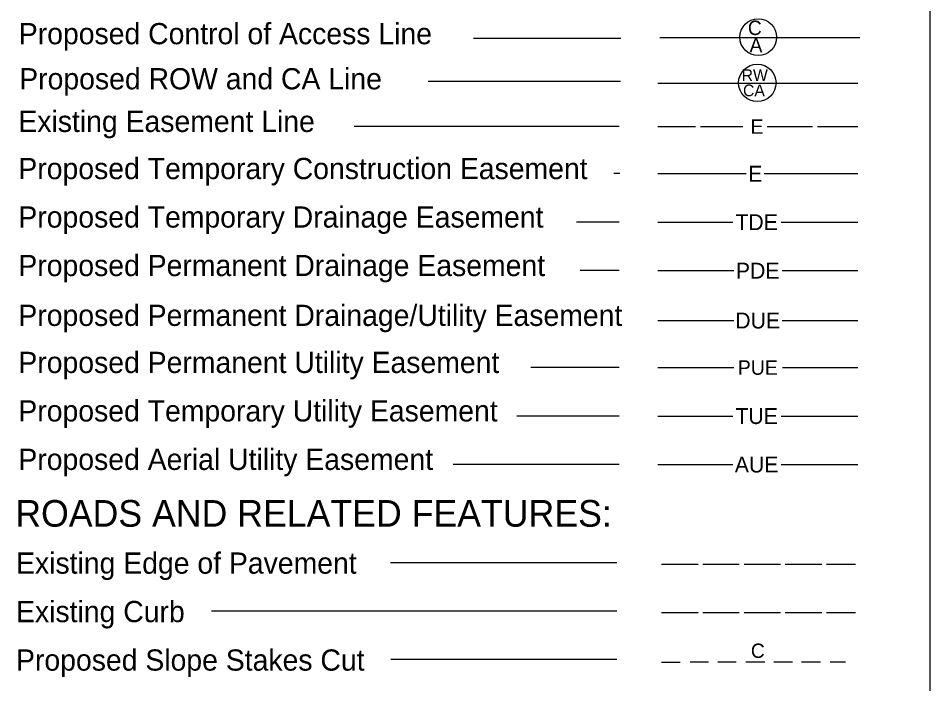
# Model space of a CAD drawing. Extents: x 1855058 to 1858918, y 1540202 to 1542502.
# Drawn here: x 1857589.3 to 1857968.6, y 1541681.9 to 1541959 of the extents above; entities that cross this region are included whole.
import ezdxf

# ---------------------------------------------------------------- set-up
doc = ezdxf.new("R2010")
doc.units = 0
for name, color, linetype in [('CTL Primary Horizontal CELL', 7, 'Continuous'), ('Exist Contamination Potential Cell', 7, 'Continuous'), ('Sheet Data Field CELL', 7, 'Continuous')]:
    doc.layers.add(name, color=color, linetype=linetype)

msp = doc.modelspace()

# ---------------------------------------------------------------- linework, layer by layer
at = {"layer": 'CTL Primary Horizontal CELL'}
for p, q in [((1857855.47, 1541833.13), (1857887.05, 1541833.13)), ((1857907.23, 1541833.13), (1857938.71, 1541833.13))]:
    msp.add_line(p, q, dxfattribs=at)
at = {"layer": 'Exist Contamination Potential Cell'}
msp.add_line((1857968.6, 1542464.27), (1857968.58, 1541439.27), dxfattribs=at)
at = {"layer": 'Sheet Data Field CELL'}
for p, q in [((1857840.04, 1541950.58), (1857778.79, 1541950.58)), ((1857856.22, 1541950.96), (1857939.45, 1541950.96)), ((1857839.94, 1541932.66), (1857759.87, 1541932.66)), ((1857855.48, 1541931.88), (1857938.72, 1541931.88)), ((1857839.3, 1541913.88), (1857729.07, 1541913.88)), ((1857855.47, 1541913.88), (1857871.12, 1541913.88)), ((1857873.14, 1541913.88), (1857890.8, 1541913.88)), ((1857900.89, 1541913.88), (1857919.81, 1541913.88)), ((1857921.82, 1541913.88), (1857938.71, 1541913.88)), ((1857839.69, 1541894.25), (1857837.15, 1541894.25)), ((1857855.47, 1541894.25), (1857858.11, 1541894.25)), ((1857858.11, 1541894.25), (1857892.16, 1541894.25)), ((1857899.73, 1541894.25), (1857933.78, 1541894.25)), ((1857933.78, 1541894.25), (1857938.71, 1541894.25)), ((1857839.3, 1541874.07), (1857821.65, 1541874.07)), ((1857855.47, 1541874.07), (1857858.85, 1541874.07)), ((1857858.85, 1541874.07), (1857886.6, 1541874.07)), ((1857906.78, 1541874.07), (1857934.52, 1541874.07)), ((1857934.52, 1541874.07), (1857938.71, 1541874.07)), ((1857839.3, 1541853.89), (1857823.15, 1541853.89)), ((1857855.47, 1541853.89), (1857859.31, 1541853.89)), ((1857859.31, 1541853.89), (1857887.05, 1541853.89)), ((1857907.23, 1541853.89), (1857934.98, 1541853.89)), ((1857934.98, 1541853.89), (1857938.71, 1541853.89)), ((1857839.3, 1541813.53), (1857802.56, 1541813.53)), ((1857855.47, 1541813.53), (1857859.35, 1541813.53)), ((1857859.35, 1541813.53), (1857887.09, 1541813.53)), ((1857907.27, 1541813.53), (1857935.02, 1541813.53)), ((1857935.02, 1541813.53), (1857938.71, 1541813.53)), ((1857839.3, 1541793.35), (1857796.79, 1541793.35)), ((1857855.47, 1541793.35), (1857858.85, 1541793.35)), ((1857858.85, 1541793.35), (1857886.6, 1541793.35)), ((1857906.78, 1541793.35), (1857934.52, 1541793.35)), ((1857934.52, 1541793.35), (1857938.71, 1541793.35)), ((1857839.3, 1541773.17), (1857770.23, 1541773.17)), ((1857855.47, 1541773.17), (1857858.85, 1541773.17)), ((1857858.85, 1541773.17), (1857886.6, 1541773.17)), ((1857906.78, 1541773.17), (1857934.52, 1541773.17)), ((1857934.52, 1541773.17), (1857938.71, 1541773.17)), ((1857838.33, 1541732.28), (1857744.26, 1541732.28)), ((1857857.03, 1541731.7), (1857872.16, 1541731.7)), ((1857874.18, 1541731.7), (1857889.31, 1541731.7)), ((1857891.33, 1541731.7), (1857906.46, 1541731.7)), ((1857908.48, 1541731.7), (1857923.62, 1541731.7)), ((1857925.63, 1541731.7), (1857937.74, 1541731.7)), ((1857838.33, 1541712.1), (1857669.69, 1541712.1)), ((1857857.03, 1541711.52), (1857872.16, 1541711.52)), ((1857874.18, 1541711.52), (1857889.31, 1541711.52)), ((1857891.33, 1541711.52), (1857906.46, 1541711.52)), ((1857908.48, 1541711.52), (1857923.62, 1541711.52)), ((1857925.63, 1541711.52), (1857937.74, 1541711.52)), ((1857838.33, 1541691.92), (1857744.31, 1541691.92)), ((1857857.03, 1541690.86), (1857864.69, 1541690.86)), ((1857876.5, 1541690.86), (1857868.88, 1541690.86)), ((1857888.1, 1541690.86), (1857880.43, 1541690.86)), ((1857899.96, 1541690.86), (1857892.09, 1541690.86)), ((1857911.51, 1541690.86), (1857903.69, 1541690.86)), ((1857923.16, 1541690.86), (1857915.24, 1541690.86)), ((1857933.55, 1541690.86), (1857927.1, 1541690.86))]:
    msp.add_line(p, q, dxfattribs=at)
for centre, radius in [((1857897.23, 1541951.07), 7.65), ((1857896.84, 1541932.04), 7.79)]:
    msp.add_circle(centre, radius, dxfattribs=at)

# ---------------------------------------------------------------- texts
at = {"layer": 'CTL Primary Horizontal CELL'}
msp.add_text('DUE', height=6.608, dxfattribs=at).set_placement((1857887.66, 1541829.8))
at = {"layer": 'Sheet Data Field CELL'}
for s, height, p in [('Proposed Control of Access Line', 8.8282, (1857589.53, 1541948.13)), ('C', 5.99, (1857892.9, 1541951.97)), ('A', 5.99, (1857893.61, 1541944.77)), ('Proposed ROW and CA Line', 8.8282, (1857589.7, 1541929.35)), ('RW', 4.882, (1857890.33, 1541932.81)), ('CA', 4.882, (1857890.9, 1541926.47)), ('Existing Easement Line', 8.8282, (1857589.34, 1541911.6)), ('E', 6.05, (1857894.03, 1541910.85)), ('Proposed Temporary Construction Easement', 8.8282, (1857589.34, 1541891.97)), ('E', 6.61, (1857893.02, 1541890.92)), ('Proposed Temporary Drainage Easement', 8.8282, (1857589.34, 1541871.79)), ('TDE', 6.608, (1857887.72, 1541870.74)), ('Proposed Permanent Drainage Easement', 8.8282, (1857589.34, 1541851.61)), ('PDE', 6.608, (1857887.91, 1541850.56)), ('Proposed Permanent Drainage/Utility Easement', 8.8282, (1857589.34, 1541830.85)), ('Proposed Permanent Utility Easement', 8.8282, (1857589.34, 1541811.24)), ('PUE', 6.054, (1857888.71, 1541810.5)), ('Proposed Temporary Utility Easement', 8.8282, (1857589.34, 1541791.07)), ('TUE', 6.608, (1857887.72, 1541790.02)), ('Proposed Aerial Utility Easement', 8.8282, (1857589.34, 1541770.89)), ('AUE', 6.608, (1857887.46, 1541769.84)), ('ROADS AND RELATED FEATURES:', 11.0983, (1857588.06, 1541747.26)), ('Existing Edge of Pavement', 8.8282, (1857588.37, 1541727.69)), ('Existing Curb', 8.8282, (1857588.37, 1541707.51)), ('C', 5.98, (1857894.15, 1541692.62)), ('Proposed Slope Stakes Cut', 8.8282, (1857588.37, 1541687.33))]:
    msp.add_text(s, height=height, dxfattribs=at).set_placement(p)

doc.saveas('drawing.dxf')
